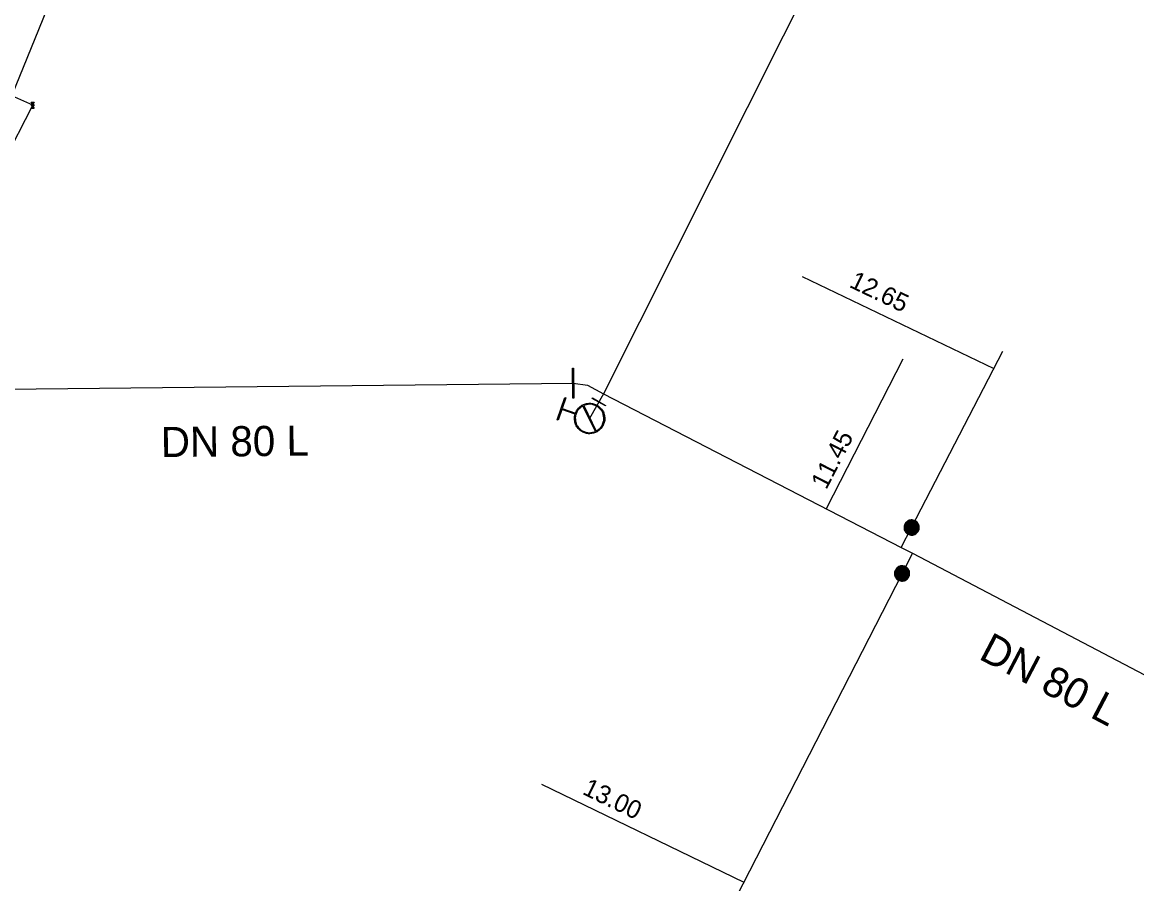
# Model space of a CAD drawing. Extents: x -820257 to -819974, y -1070894 to -1070484.
# Drawn here: x -820183 to -820109.2, y -1070745.2 to -1070688.1 of the extents above; entities that cross this region are included whole.
import ezdxf

# ---------------------------------------------------------------- set-up
doc = ezdxf.new("R2010")
doc.units = 0
for name, color, linetype in [('Hyd-odbočka', 7, 'Continuous'), ('Hyd-šoupě', 7, 'Continuous'), ('Hydrant', 7, 'Continuous'), ('Lomový bod vodovodu', 7, 'Continuous'), ('Oměrka vodovodu', 7, 'Continuous'), ('Oměrka-text', 7, 'Continuous'), ('Přípojka vodovodu', 7, 'Continuous'), ('Přípojkový uzávěr', 7, 'Continuous'), ('Roz-řad', 7, 'Continuous'), ('Roz-řad-popis základní', 7, 'Continuous'), ('Řad-šoupě', 7, 'Continuous')]:
    doc.layers.add(name, color=color, linetype=linetype)

msp = doc.modelspace()

# ---------------------------------------------------------------- linework, layer by layer
at = {"layer": 'Hyd-odbočka'}
msp.add_line((-820144.508, -1070712.712), (-820145.438, -1070714.35), dxfattribs=at)
at = {"layer": 'Hyd-šoupě'}
msp.add_lwpolyline([(-820145.243, -1070712.993), (-820144.373, -1070713.487), (-820144.389, -1070713.514), (-820145.258, -1070713.02), (-820145.243, -1070712.993)], dxfattribs=at)
at = {"layer": 'Hydrant'}
for points in [[(-820146.394, -1070714.056), (-820147.281, -1070713.753), (-820147.524, -1070714.462), (-820147.583, -1070714.442), (-820147.077, -1070712.964), (-820147.018, -1070712.984), (-820147.261, -1070713.693), (-820146.374, -1070713.997)], [(-820145.051, -1070715.206), (-820145.878, -1070713.52)], [(-820145.824, -1070713.493), (-820144.995, -1070715.18)]]:
    msp.add_lwpolyline(points, dxfattribs=at)
for points in [[(-820146.374, -1070713.997), (-820146.29, -1070713.776), (-820146.102, -1070713.602), (-820145.903, -1070713.419), (-820145.632, -1070713.369), (-820145.362, -1070713.319), (-820145.114, -1070713.404), (-820144.868, -1070713.488), (-820144.685, -1070713.69), (-820144.503, -1070713.891), (-820144.455, -1070714.16), (-820144.407, -1070714.428), (-820144.491, -1070714.673), (-820144.575, -1070714.919), (-820144.777, -1070715.102), (-820144.979, -1070715.285), (-820145.247, -1070715.333), (-820145.515, -1070715.38), (-820145.761, -1070715.296), (-820146.009, -1070715.211), (-820146.192, -1070715.006), (-820146.376, -1070714.801), (-820146.421, -1070714.534), (-820146.464, -1070714.284), (-820146.394, -1070714.056)], [(-820145.878, -1070713.52), (-820145.977, -1070713.573), (-820146.061, -1070713.65), (-820146.248, -1070713.823), (-820146.325, -1070714.047), (-820146.401, -1070714.27), (-820146.359, -1070714.522), (-820146.317, -1070714.774), (-820146.145, -1070714.965), (-820145.974, -1070715.157), (-820145.741, -1070715.237), (-820145.51, -1070715.316), (-820145.259, -1070715.27), (-820145.149, -1070715.251), (-820145.051, -1070715.206)], [(-820144.995, -1070715.18), (-820144.901, -1070715.13), (-820144.82, -1070715.054), (-820144.629, -1070714.884), (-820144.55, -1070714.653), (-820144.471, -1070714.422), (-820144.516, -1070714.171), (-820144.561, -1070713.919), (-820144.732, -1070713.73), (-820144.903, -1070713.542), (-820145.134, -1070713.463), (-820145.367, -1070713.383), (-820145.621, -1070713.431), (-820145.729, -1070713.451), (-820145.824, -1070713.493)]]:
    msp.add_open_spline(points, degree=3, dxfattribs=at)
at = {"layer": 'Lomový bod vodovodu'}
for points in [[(-820182.368, -1070693.536), (-820182.43, -1070693.4), (-820182.23, -1070693.4), (-820182.293, -1070693.536)], [(-820182.308, -1070693.529), (-820182.254, -1070693.413), (-820182.408, -1070693.413), (-820182.353, -1070693.529)], [(-820182.293, -1070693.664), (-820182.23, -1070693.8), (-820182.43, -1070693.8), (-820182.368, -1070693.664)], [(-820182.353, -1070693.671), (-820182.408, -1070693.788), (-820182.254, -1070693.788), (-820182.308, -1070693.671)], [(-820182.362, -1070693.653), (-820182.338, -1070693.6), (-820182.362, -1070693.547)], [(-820182.348, -1070693.54), (-820182.33, -1070693.578), (-820182.313, -1070693.54)], [(-820182.313, -1070693.66), (-820182.33, -1070693.622), (-820182.348, -1070693.66)], [(-820182.298, -1070693.547), (-820182.322, -1070693.6), (-820182.298, -1070693.653)]]:
    msp.add_lwpolyline(points, dxfattribs=at)
for points in [[(-820182.368, -1070693.664), (-820182.385, -1070693.655), (-820182.395, -1070693.637), (-820182.405, -1070693.62), (-820182.405, -1070693.6), (-820182.405, -1070693.58), (-820182.395, -1070693.563), (-820182.385, -1070693.545), (-820182.368, -1070693.536)], [(-820182.362, -1070693.547), (-820182.376, -1070693.555), (-820182.384, -1070693.569), (-820182.392, -1070693.584), (-820182.392, -1070693.6), (-820182.392, -1070693.616), (-820182.384, -1070693.631), (-820182.376, -1070693.645), (-820182.362, -1070693.653)], [(-820182.353, -1070693.529), (-820182.342, -1070693.525), (-820182.33, -1070693.525), (-820182.319, -1070693.525), (-820182.308, -1070693.529)], [(-820182.308, -1070693.671), (-820182.318, -1070693.675), (-820182.33, -1070693.675), (-820182.342, -1070693.675), (-820182.353, -1070693.671)], [(-820182.313, -1070693.54), (-820182.321, -1070693.538), (-820182.33, -1070693.538), (-820182.339, -1070693.538), (-820182.348, -1070693.54)], [(-820182.348, -1070693.66), (-820182.339, -1070693.662), (-820182.33, -1070693.662), (-820182.321, -1070693.662), (-820182.313, -1070693.66)], [(-820182.298, -1070693.653), (-820182.284, -1070693.645), (-820182.276, -1070693.631), (-820182.268, -1070693.616), (-820182.268, -1070693.6), (-820182.268, -1070693.584), (-820182.276, -1070693.569), (-820182.284, -1070693.555), (-820182.298, -1070693.547)], [(-820182.293, -1070693.536), (-820182.275, -1070693.545), (-820182.265, -1070693.563), (-820182.255, -1070693.58), (-820182.255, -1070693.6), (-820182.255, -1070693.62), (-820182.265, -1070693.637), (-820182.275, -1070693.655), (-820182.293, -1070693.664)]]:
    msp.add_open_spline(points, degree=3, dxfattribs=at)
at = {"layer": 'Oměrka vodovodu'}
for p, q in [((-820131.359, -1070704.939), (-820118.65, -1070711.047)), ((-820124.676, -1070710.411), (-820129.769, -1070720.332)), ((-820148.616, -1070738.573), (-820135.216, -1070745.066))]:
    msp.add_line(p, q, dxfattribs=at)
at = {"layer": 'Přípojka vodovodu'}
for points in [[(-820124.791, -1070722.905), (-820124.101, -1070721.573), (-820118.055, -1070709.899)], [(-820124.049, -1070723.282), (-820124.733, -1070724.617), (-820136.162, -1070746.911)]]:
    msp.add_lwpolyline(points, dxfattribs=at)
at = {"layer": 'Přípojkový uzávěr'}
for points in [[(-820124.545, -1070721.344), (-820124.487, -1070721.232), (-820124.375, -1070721.155), (-820124.263, -1070721.079), (-820124.125, -1070721.074), (-820123.987, -1070721.069), (-820123.871, -1070721.129), (-820123.755, -1070721.189), (-820123.68, -1070721.302), (-820123.605, -1070721.415), (-820123.601, -1070721.552), (-820123.597, -1070721.688), (-820123.657, -1070721.803), (-820123.717, -1070721.918), (-820123.83, -1070721.994), (-820123.943, -1070722.069), (-820124.079, -1070722.073), (-820124.215, -1070722.077), (-820124.331, -1070722.017), (-820124.447, -1070721.957), (-820124.523, -1070721.842), (-820124.599, -1070721.727), (-820124.601, -1070721.592), (-820124.603, -1070721.456), (-820124.545, -1070721.344)], [(-820124.504, -1070721.365), (-820124.556, -1070721.467), (-820124.554, -1070721.59), (-820124.552, -1070721.713), (-820124.483, -1070721.817), (-820124.414, -1070721.921), (-820124.309, -1070721.976), (-820124.205, -1070722.03), (-820124.082, -1070722.026), (-820123.959, -1070722.023), (-820123.856, -1070721.954), (-820123.753, -1070721.886), (-820123.699, -1070721.782), (-820123.645, -1070721.677), (-820123.648, -1070721.553), (-820123.651, -1070721.43), (-820123.72, -1070721.327), (-820123.788, -1070721.225), (-820123.892, -1070721.171), (-820123.998, -1070721.116), (-820124.123, -1070721.121), (-820124.248, -1070721.125), (-820124.35, -1070721.194), (-820124.451, -1070721.264), (-820124.504, -1070721.365)], [(-820124.473, -1070721.381), (-820124.425, -1070721.287), (-820124.331, -1070721.223), (-820124.237, -1070721.159), (-820124.121, -1070721.155), (-820124.005, -1070721.151), (-820123.908, -1070721.201), (-820123.811, -1070721.251), (-820123.748, -1070721.346), (-820123.685, -1070721.441), (-820123.682, -1070721.555), (-820123.679, -1070721.669), (-820123.729, -1070721.766), (-820123.779, -1070721.862), (-820123.874, -1070721.926), (-820123.969, -1070721.989), (-820124.083, -1070721.992), (-820124.197, -1070721.995), (-820124.293, -1070721.945), (-820124.391, -1070721.895), (-820124.455, -1070721.799), (-820124.518, -1070721.702), (-820124.52, -1070721.588), (-820124.522, -1070721.474), (-820124.473, -1070721.381)], [(-820124.434, -1070721.401), (-820124.506, -1070721.54), (-820124.459, -1070721.687), (-820124.411, -1070721.835), (-820124.273, -1070721.906), (-820124.135, -1070721.978), (-820123.987, -1070721.931), (-820123.839, -1070721.883), (-820123.768, -1070721.746), (-820123.697, -1070721.608), (-820123.743, -1070721.46), (-820123.79, -1070721.312), (-820123.928, -1070721.24), (-820124.066, -1070721.169), (-820124.214, -1070721.215), (-820124.362, -1070721.261), (-820124.434, -1070721.401)], [(-820124.394, -1070721.423), (-820124.331, -1070721.301), (-820124.202, -1070721.26), (-820124.072, -1070721.219), (-820123.951, -1070721.282), (-820123.83, -1070721.345), (-820123.789, -1070721.474), (-820123.748, -1070721.603), (-820123.811, -1070721.724), (-820123.874, -1070721.846), (-820124.003, -1070721.887), (-820124.132, -1070721.928), (-820124.253, -1070721.865), (-820124.374, -1070721.802), (-820124.415, -1070721.673), (-820124.457, -1070721.544), (-820124.394, -1070721.423)], [(-820124.359, -1070721.441), (-820124.414, -1070721.547), (-820124.378, -1070721.661), (-820124.341, -1070721.775), (-820124.235, -1070721.83), (-820124.129, -1070721.885), (-820124.015, -1070721.849), (-820123.901, -1070721.813), (-820123.846, -1070721.706), (-820123.791, -1070721.6), (-820123.827, -1070721.486), (-820123.863, -1070721.372), (-820123.97, -1070721.317), (-820124.076, -1070721.262), (-820124.19, -1070721.298), (-820124.303, -1070721.334), (-820124.359, -1070721.441)], [(-820124.323, -1070721.459), (-820124.275, -1070721.365), (-820124.176, -1070721.334), (-820124.078, -1070721.303), (-820123.986, -1070721.351), (-820123.894, -1070721.399), (-820123.863, -1070721.498), (-820123.831, -1070721.596), (-820123.879, -1070721.688), (-820123.927, -1070721.78), (-820124.025, -1070721.811), (-820124.124, -1070721.843), (-820124.216, -1070721.795), (-820124.308, -1070721.747), (-820124.34, -1070721.649), (-820124.371, -1070721.551), (-820124.323, -1070721.459)], [(-820124.282, -1070721.48), (-820124.321, -1070721.555), (-820124.296, -1070721.635), (-820124.27, -1070721.715), (-820124.195, -1070721.754), (-820124.12, -1070721.792), (-820124.04, -1070721.767), (-820123.96, -1070721.742), (-820123.921, -1070721.667), (-820123.883, -1070721.592), (-820123.908, -1070721.512), (-820123.933, -1070721.432), (-820124.008, -1070721.393), (-820124.083, -1070721.354), (-820124.163, -1070721.379), (-820124.243, -1070721.405), (-820124.282, -1070721.48)], [(-820124.251, -1070721.496), (-820124.219, -1070721.433), (-820124.153, -1070721.412), (-820124.087, -1070721.391), (-820124.024, -1070721.424), (-820123.962, -1070721.456), (-820123.941, -1070721.522), (-820123.92, -1070721.589), (-820123.952, -1070721.651), (-820123.984, -1070721.713), (-820124.051, -1070721.734), (-820124.117, -1070721.755), (-820124.179, -1070721.723), (-820124.242, -1070721.691), (-820124.263, -1070721.624), (-820124.284, -1070721.558), (-820124.251, -1070721.496)], [(-820124.212, -1070721.516), (-820124.236, -1070721.562), (-820124.22, -1070721.611), (-820124.204, -1070721.66), (-820124.159, -1070721.684), (-820124.113, -1070721.708), (-820124.063, -1070721.692), (-820124.014, -1070721.677), (-820123.99, -1070721.631), (-820123.966, -1070721.585), (-820123.982, -1070721.535), (-820123.998, -1070721.486), (-820124.044, -1070721.462), (-820124.09, -1070721.438), (-820124.139, -1070721.454), (-820124.188, -1070721.469), (-820124.212, -1070721.516)], [(-820124.171, -1070721.538), (-820124.155, -1070721.508), (-820124.125, -1070721.498), (-820124.095, -1070721.489), (-820124.065, -1070721.504), (-820124.037, -1070721.519), (-820124.027, -1070721.549), (-820124.017, -1070721.58), (-820124.032, -1070721.609), (-820124.047, -1070721.638), (-820124.078, -1070721.648), (-820124.109, -1070721.658), (-820124.137, -1070721.643), (-820124.167, -1070721.628), (-820124.176, -1070721.597), (-820124.185, -1070721.566), (-820124.171, -1070721.538)], [(-820124.143, -1070721.552), (-820124.152, -1070721.569), (-820124.146, -1070721.588), (-820124.141, -1070721.606), (-820124.123, -1070721.615), (-820124.105, -1070721.624), (-820124.087, -1070721.618), (-820124.069, -1070721.612), (-820124.06, -1070721.595), (-820124.05, -1070721.577), (-820124.056, -1070721.559), (-820124.062, -1070721.541), (-820124.08, -1070721.532), (-820124.097, -1070721.523), (-820124.116, -1070721.528), (-820124.134, -1070721.534), (-820124.143, -1070721.552)], [(-820125.179, -1070724.389), (-820125.122, -1070724.277), (-820125.01, -1070724.2), (-820124.898, -1070724.123), (-820124.76, -1070724.118), (-820124.622, -1070724.113), (-820124.505, -1070724.172), (-820124.39, -1070724.231), (-820124.314, -1070724.344), (-820124.238, -1070724.457), (-820124.234, -1070724.593), (-820124.23, -1070724.729), (-820124.289, -1070724.845), (-820124.348, -1070724.961), (-820124.461, -1070725.037), (-820124.574, -1070725.113), (-820124.71, -1070725.117), (-820124.846, -1070725.121), (-820124.962, -1070725.062), (-820125.078, -1070725.002), (-820125.154, -1070724.888), (-820125.231, -1070724.773), (-820125.234, -1070724.637), (-820125.237, -1070724.502), (-820125.179, -1070724.389)], [(-820125.137, -1070724.411), (-820125.189, -1070724.512), (-820125.187, -1070724.635), (-820125.184, -1070724.759), (-820125.115, -1070724.862), (-820125.046, -1070724.966), (-820124.94, -1070725.02), (-820124.835, -1070725.074), (-820124.712, -1070725.07), (-820124.589, -1070725.066), (-820124.487, -1070724.997), (-820124.384, -1070724.928), (-820124.331, -1070724.824), (-820124.277, -1070724.719), (-820124.281, -1070724.595), (-820124.285, -1070724.472), (-820124.353, -1070724.37), (-820124.422, -1070724.268), (-820124.527, -1070724.214), (-820124.632, -1070724.16), (-820124.757, -1070724.165), (-820124.883, -1070724.17), (-820124.984, -1070724.239), (-820125.085, -1070724.309), (-820125.137, -1070724.411)], [(-820125.107, -1070724.426), (-820125.059, -1070724.332), (-820124.965, -1070724.268), (-820124.871, -1070724.204), (-820124.756, -1070724.199), (-820124.64, -1070724.194), (-820124.542, -1070724.244), (-820124.445, -1070724.294), (-820124.382, -1070724.388), (-820124.318, -1070724.483), (-820124.315, -1070724.597), (-820124.311, -1070724.711), (-820124.361, -1070724.809), (-820124.411, -1070724.905), (-820124.505, -1070724.969), (-820124.6, -1070725.033), (-820124.714, -1070725.036), (-820124.828, -1070725.04), (-820124.925, -1070724.99), (-820125.022, -1070724.94), (-820125.086, -1070724.844), (-820125.151, -1070724.748), (-820125.153, -1070724.634), (-820125.155, -1070724.52), (-820125.107, -1070724.426)], [(-820125.068, -1070724.447), (-820125.139, -1070724.586), (-820125.091, -1070724.733), (-820125.043, -1070724.88), (-820124.904, -1070724.951), (-820124.766, -1070725.022), (-820124.619, -1070724.974), (-820124.471, -1070724.926), (-820124.401, -1070724.789), (-820124.329, -1070724.65), (-820124.377, -1070724.502), (-820124.424, -1070724.354), (-820124.562, -1070724.283), (-820124.701, -1070724.212), (-820124.849, -1070724.259), (-820124.996, -1070724.306), (-820125.068, -1070724.447)], [(-820125.027, -1070724.468), (-820124.965, -1070724.346), (-820124.836, -1070724.304), (-820124.707, -1070724.263), (-820124.585, -1070724.325), (-820124.464, -1070724.388), (-820124.423, -1070724.517), (-820124.381, -1070724.646), (-820124.443, -1070724.767), (-820124.506, -1070724.889), (-820124.635, -1070724.93), (-820124.764, -1070724.972), (-820124.885, -1070724.909), (-820125.006, -1070724.847), (-820125.048, -1070724.718), (-820125.09, -1070724.589), (-820125.027, -1070724.468)], [(-820124.992, -1070724.486), (-820125.047, -1070724.593), (-820125.01, -1070724.706), (-820124.973, -1070724.82), (-820124.867, -1070724.874), (-820124.76, -1070724.929), (-820124.647, -1070724.892), (-820124.533, -1070724.856), (-820124.478, -1070724.749), (-820124.424, -1070724.643), (-820124.46, -1070724.529), (-820124.497, -1070724.415), (-820124.604, -1070724.361), (-820124.71, -1070724.306), (-820124.823, -1070724.342), (-820124.937, -1070724.378), (-820124.992, -1070724.486)], [(-820124.957, -1070724.503), (-820124.909, -1070724.41), (-820124.81, -1070724.379), (-820124.712, -1070724.347), (-820124.619, -1070724.395), (-820124.527, -1070724.442), (-820124.496, -1070724.54), (-820124.464, -1070724.639), (-820124.512, -1070724.731), (-820124.559, -1070724.823), (-820124.657, -1070724.855), (-820124.755, -1070724.887), (-820124.847, -1070724.84), (-820124.94, -1070724.792), (-820124.972, -1070724.694), (-820125.004, -1070724.596), (-820124.957, -1070724.503)], [(-820124.915, -1070724.525), (-820124.954, -1070724.6), (-820124.928, -1070724.68), (-820124.902, -1070724.759), (-820124.827, -1070724.798), (-820124.752, -1070724.836), (-820124.672, -1070724.811), (-820124.592, -1070724.785), (-820124.554, -1070724.71), (-820124.515, -1070724.635), (-820124.541, -1070724.555), (-820124.567, -1070724.475), (-820124.642, -1070724.436), (-820124.717, -1070724.398), (-820124.797, -1070724.424), (-820124.877, -1070724.449), (-820124.915, -1070724.525)], [(-820124.884, -1070724.54), (-820124.852, -1070724.478), (-820124.786, -1070724.456), (-820124.72, -1070724.435), (-820124.658, -1070724.467), (-820124.595, -1070724.499), (-820124.574, -1070724.566), (-820124.553, -1070724.632), (-820124.585, -1070724.694), (-820124.617, -1070724.757), (-820124.683, -1070724.778), (-820124.749, -1070724.799), (-820124.811, -1070724.767), (-820124.874, -1070724.735), (-820124.895, -1070724.669), (-820124.916, -1070724.603), (-820124.884, -1070724.54)], [(-820124.845, -1070724.56), (-820124.869, -1070724.606), (-820124.853, -1070724.656), (-820124.837, -1070724.705), (-820124.791, -1070724.728), (-820124.745, -1070724.752), (-820124.696, -1070724.736), (-820124.646, -1070724.72), (-820124.623, -1070724.674), (-820124.599, -1070724.628), (-820124.615, -1070724.579), (-820124.631, -1070724.529), (-820124.677, -1070724.506), (-820124.723, -1070724.482), (-820124.772, -1070724.498), (-820124.821, -1070724.513), (-820124.845, -1070724.56)], [(-820124.804, -1070724.582), (-820124.788, -1070724.552), (-820124.758, -1070724.542), (-820124.728, -1070724.533), (-820124.698, -1070724.548), (-820124.67, -1070724.563), (-820124.66, -1070724.593), (-820124.649, -1070724.623), (-820124.665, -1070724.653), (-820124.679, -1070724.682), (-820124.71, -1070724.692), (-820124.741, -1070724.702), (-820124.77, -1070724.687), (-820124.799, -1070724.672), (-820124.809, -1070724.641), (-820124.818, -1070724.61), (-820124.804, -1070724.582)], [(-820124.776, -1070724.596), (-820124.785, -1070724.613), (-820124.779, -1070724.632), (-820124.773, -1070724.65), (-820124.755, -1070724.659), (-820124.738, -1070724.668), (-820124.72, -1070724.662), (-820124.701, -1070724.656), (-820124.692, -1070724.639), (-820124.683, -1070724.621), (-820124.689, -1070724.603), (-820124.695, -1070724.585), (-820124.713, -1070724.576), (-820124.731, -1070724.567), (-820124.749, -1070724.572), (-820124.767, -1070724.578), (-820124.776, -1070724.596)]]:
    msp.add_open_spline(points, degree=3, dxfattribs=at)
at = {"layer": 'Roz-řad'}
for points in [[(-820107.099, -1070638.195), (-820120.711, -1070665.309), (-820144.508, -1070712.712)], [(-820203.65, -1070730.98), (-820194.91, -1070715.48), (-820193.87, -1070716.11), (-820182.33, -1070693.6), (-820183.71, -1070692.98), (-820178.78, -1070680.85), (-820175.51, -1070672.3), (-820175.3, -1070660.58), (-820174.05, -1070658.3)], [(-820219.039, -1070712.339), (-820217.709, -1070712.762), (-820146.528, -1070712.014)], [(-820146.528, -1070712.014), (-820145.584, -1070712.134), (-820144.508, -1070712.712)], [(-820144.508, -1070712.712), (-820124.791, -1070722.905), (-820124.049, -1070723.282), (-820091.962, -1070740.107)]]:
    msp.add_lwpolyline(points, dxfattribs=at)
at = {"layer": 'Řad-šoupě'}
msp.add_lwpolyline([(-820146.506, -1070711.013), (-820146.485, -1070713.013), (-820146.548, -1070713.013), (-820146.569, -1070711.013), (-820146.506, -1070711.013)], dxfattribs=at)

# ---------------------------------------------------------------- texts
at = {"layer": 'Oměrka-text'}
for s, rotation, p in [('12.65', 334.33084, (-820128.293, -1070705.618)), ('11.45', 62.82603, (-820129.756, -1070719.118)), ('13.00', 334.14738, (-820145.977, -1070739.202))]:
    msp.add_text(s, height=1.2, rotation=rotation, dxfattribs=at).set_placement(p)
at = {"layer": 'Roz-řad-popis základní'}
for rotation, p in [(0.60206, (-820173.833, -1070716.914)), (332.32944, (-820119.73, -1070730.237))]:
    msp.add_text('DN 80 L', height=2, rotation=rotation, dxfattribs=at).set_placement(p)

doc.saveas('drawing.dxf')
